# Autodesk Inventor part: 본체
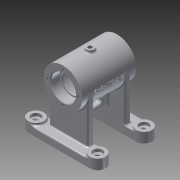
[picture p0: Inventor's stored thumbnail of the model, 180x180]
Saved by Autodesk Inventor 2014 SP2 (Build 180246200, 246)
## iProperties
Created: 2015-11
Part Number: 본체
Material: 알루미늄 6061
Document SubType Name: Modeling
Designer: 702
Density: 2.71 g/cm^3
Appearance: 알루미늄 - 평지
Mass: 360.715 g
Surface Area: 458.118 cm^2
Volume: 133.105 cm^3
Author: 702
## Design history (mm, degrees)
sketch "스케치1"
  geometry: L1 (-35, 25)-(35, 25); L2 (-35, 25)-(-35, 16); L3 (-35, 16)-(-23, 16); L4 (-23, 16)-(-23, 14); L5 (-23, 14)-(-21, 14); L6 (-21, 14)-(-21, 21); L7 (-21, 21)-(21, 21); L8 (21, 21)-(21, 14); L9 (21, 14)-(23, 14); L10 (23, 14)-(23, 16); L11 (23, 16)-(35, 16); L12 (35, 16)-(35, 25); L13 (-32.029, 0)-(31.894, 0); L14 (-49, 0)-(49, 0) reference; 1 further point
  constraints: 26 end point, 7 parallel, 3 perpendicular, 1 collinear, 1 horizontal, 1 point on line, 1 vertical
  dimensions: "d0" = 25 distance between parallel lines of L13 L1; "d1" = 16 distance from line of L13.end L11; "d2" = 21 distance from line of point (0, 0) L7; "d3" = 16 distance from line of point (0, 0) L3; "d4" = 70 distance between parallel lines of L12 L2; "d5" = 35 distance from line of point (0, 0) L2; "d6" = 12 distance between parallel lines of L4 L2; "d7" = 12 distance between parallel lines of L10 L12; "d8" = 42 distance between parallel lines of L8 L6; "d9" = 21 distance from line of point (0, 0) L6; "d10" = 14 distance from line of point (0, 0) L5; "d11" = 14 distance from line of point (0, 0) L9
revolve "회전1" sketch "스케치1" stored, may be unused: angle "d12" = 90 deg
node "작업 평면1"
sketch "스케치2"
  geometry: L1 (-25, 0)-(-25, -68); L2 (25, 0)-(25, -68); L3 (-25, -68)-(25, -68); A1 r 25 centre (0, 0) between (-25, 0) and (25, 0) reference; A2 r 25 centre (0, 0) between (-25, 0) and (25, 0); 1 further point
  constraints: 6 end point, 4 point on circle, 2 tangent, 1 centre point, 1 coincident, 1 concentric, 1 parallel, 1 vertical
  dimensions: "d14" = 68 distance of L1.start L1.end; "d15" = 68 distance of L2.start L2.end
extrude "돌출1" join sketch "스케치2" distance "d16" = 8; taper "d17" = 0 deg
sketch "스케치3"
  geometry: L1 (0, 0)-(50, 0) reference; L2 (50, 0)-(50, 8) reference; L3 (0, 8)-(50, 8) reference; L4 (0, 0)-(0, 8) reference; L5 (-15, 0)-(65, 0); L6 (-15, 20)-(65, 20); A1 r 10 centre (-15, 10) between (-15, 0) and (-15, 20); A2 r 10 centre (65, 10) between (65, 0) and (65, 20); 1 further point
  constraints: 4 end point, 4 point on circle, 4 tangent, 2 centre point, 1 collinear
  dimensions: "d18" = 20 diameter of A1; "d19" = 20 diameter of A2; "d20" = 80 distance of A2.centre A1.centre; "d21" = 40 horizontal distance of point (25, -20) A1.centre
extrude "돌출2" join sketch "스케치3" distance "d22" = 10; taper "d23" = 0 deg
extrude "돌출3" join sketch "스케치3" distance "d24" = 13; taper "d25" = 0 deg
sketch "스케치4"
  geometry: C1 r 10 at (0, 0) reference; 2 further points
  constraints: 1 coincident
node "작업 평면2"
sketch "스케치5"
  geometry: L1 (80, -13)-(80, 0); L2 (90, 0)-(80, 0) reference; L3 (90, 0)-(90, -13) reference; L4 (83, 0)-(83, -9); L5 (83, -9)-(86, -9); L6 (86, -9)-(86, -13); L7 (70, -13)-(90, -13) reference; L8 (86, -13)-(80, -13); L9 (83, 0)-(80, 0); L10 (80, -13)-(80, 0); 1 further point
  constraints: 14 end point, 3 parallel, 2 collinear, 2 point on line, 1 perpendicular, 1 vertical
  dimensions: "d27" = 10 distance between parallel lines of L3 L1; "d28" = 3 distance between parallel lines of L1 L4; "d29" = 6 distance between parallel lines of L1 L6; "d30" = 4 distance between parallel lines of L7 L5
revolve "회전2" sketch "스케치5" stored, may be unused: angle "d31" = 90 deg
sketch "스케치6"
  geometry: L1 (21, -21)-(-21, -21) reference; L2 (-20, -58)-(-20, 0) reference; L3 (20, -58)-(20, 0) reference; L4 (-20, -45)-(20, -45); L5 (20, -45)-(20, -21); L6 (-20, -21)-(-20, -45); L7 (-20, -21)-(20, -21); L8 (-35, -25)-(35, -25) reference; 1 further point
  constraints: 8 end point, 6 point on line, 2 collinear, 1 perpendicular
  dimensions: "d32" = 20 distance between parallel lines of L4 L8
extrude "돌출4" join sketch "스케치6" stored distance "d33" = 8; taper "d34" = 0 deg
sketch "스케치7"
  geometry: L1 (68, 20)-(68, 40) reference; L2 (31.5, 8)-(31.5, -8); L3 (38.5, 8)-(38.5, -8); L4 (25, 35)-(-25, 35) reference; A1 r 3.5 centre (35, 8) between (31.5, 8) and (38.5, 8); A2 r 3.5 centre (35, -8) between (31.5, -8) and (38.5, -8); 1 further point
  constraints: 4 end point, 4 point on circle, 4 tangent, 2 centre point
  dimensions: "d35" = 7 diameter of A1; "d36" = 7 diameter of A2; "d37" = 33 distance from line of L1 A1.centre; "d38" = 33 distance from line of L1 A2.centre (= d37); "d39" = 16 distance of A2.centre A1.centre; "d40" = 27 distance from line of A1.centre L4
extrude "돌출5" cut sketch "스케치7" distance "d41" = 8; taper "d42" = 0 deg
sketch "스케치8"
  geometry: C1 r 16 at (0, 0) reference; 1 further point
  constraints: 1 vertical alignment
  dimensions: "d43" = 20 distance of C1.centre point (0, 20)
hole "구멍1" sketch "스케치8" at (0, 20) diameter "d44" = 3.242; stored, may be unused: countersink angle "d48" = 90 deg, drill point angle "d50" = 118 deg; dims "d45" = 8, "d46" = 4, "d47" = 2, "d49" = 10
chamfer "모따기1" distance "d54" = 1; stored, may be unused: second distance "d55" = 2, angle "d56" = 45 deg
chamfer "모따기2" distance "d57" = 1; stored, may be unused: second distance "d58" = 2, angle "d59" = 45 deg
chamfer "모따기3" distance "d60" = 3; stored, may be unused: second distance "d61" = 2, angle "d62" = 45 deg
chamfer "모따기4" distance "d63" = 3; stored, may be unused: second distance "d64" = 2, angle "d65" = 45 deg
chamfer "모따기5" distance "d66" = 1; stored, may be unused: second distance "d67" = 2, angle "d68" = 45 deg
fillet "모깎기1" dims "d69" = 0.3
fillet "모깎기2" dims "d70" = 0.3
fillet "모깎기3" dims "d71" = 0.3
fillet "모깎기4" dims "d72" = 0.3
fillet "모깎기5" dims "d73" = 2
fillet "모깎기6" dims "d74" = 2
fillet "모깎기7" dims "d75" = 2
fillet "모깎기8" dims "d76" = 2
fillet "모깎기9" dims "d77" = 2
fillet "모깎기10" dims "d78" = 2
fillet "모깎기11" dims "d79" = 2
fillet "모깎기12" dims "d80" = 2
fillet "모깎기13" dims "d81" = 2
fillet "모깎기14" dims "d82" = 2
node "작업 평면4"
sketch "스케치9"
  geometry: C1 r 5 at (0, 0); 1 further point
  constraints: 1 centre point, 1 coincident
  dimensions: "d84" = 10 diameter of C1
extrude "돌출6" join sketch "스케치9" stored distance "d85" = 8; taper "d86" = 0 deg
sketch "스케치10"
  geometry: 2 further points
  constraints: 1 coincident
hole "구멍2" sketch "스케치10" at (0, 0) diameter "d87" = 4.917; stored, may be unused: countersink angle "d91" = 90 deg, drill point angle "d93" = 118 deg; dims "d88" = 15, "d89" = 4, "d90" = 2, "d92" = 15
sketch "스케치11"
  geometry: L1 (0, 0)-(-14, -24.249); L2 (0, 0)-(-57.632, 0)
  constraints: 4 end point, 1 horizontal
  dimensions: "d94" = 60 deg angle of L2 L1; "d95" = 28 distance of L1.start L1.end
node "작업 평면5"
fillet "모깎기16" dims "d107" = 2
node "작업 평면6"
sketch "스케치15"
  geometry: L1 (0, 0)-(57.811, 0); L2 (0, 0)-(14, -24.249)
  constraints: 4 end point, 1 horizontal
  dimensions: "d109" = 60 deg angle of L1 L2; "d110" = 28 distance of L1.start L2.end
node "작업 평면8"
sketch "스케치16"
  geometry: C1 r 5 at (0, 0); 1 further point
  constraints: 1 centre point, 1 coincident
  dimensions: "d111" = 10 diameter of C1
extrude "돌출8" join sketch "스케치16" stored distance "d112" = 8; taper "d113" = 0 deg
sketch "스케치17"
  geometry: C1 r 5 at (0, 0) reference; 1 further point
  constraints: 1 coincident
hole "구멍4" sketch "스케치17" at (0, 0) diameter "d114" = 4.917; stored, may be unused: countersink angle "d118" = 90 deg, drill point angle "d120" = 118 deg; dims "d115" = 15, "d116" = 4, "d117" = 2, "d119" = 15
sketch "스케치18"
  geometry: L1 (-20.592, 2.487)-(20.887, 2.487); L2 (20.887, 2.487)-(20.887, -3.517); L3 (20.887, -3.517)-(-20.592, -3.517); L4 (-20.592, -3.517)-(-20.592, 2.487); L5 (35, -25)-(35, 25) reference; L6 (-35, 25)-(35, 25) reference; 1 further point
  constraints: 2 other
  dimensions: "d121" = 35 distance from line of L5 point (0, 0) (derived); "d122" = 25 distance from line of L6 point (0, 0) (derived)
feature "엠보싱1" sketch "스케치18" dims "d123" = 0.5, "d124" = 0
fillet "모깎기17" dims "d125" = 2
node "솔리드1"
mirror "대칭1"
pattern_circular "원형 패턴1" dims angle "d52" = 360 deg
mirror "대칭3"
mirror "대칭4"
other parameters: "d83" = 28, "d108" = 25
